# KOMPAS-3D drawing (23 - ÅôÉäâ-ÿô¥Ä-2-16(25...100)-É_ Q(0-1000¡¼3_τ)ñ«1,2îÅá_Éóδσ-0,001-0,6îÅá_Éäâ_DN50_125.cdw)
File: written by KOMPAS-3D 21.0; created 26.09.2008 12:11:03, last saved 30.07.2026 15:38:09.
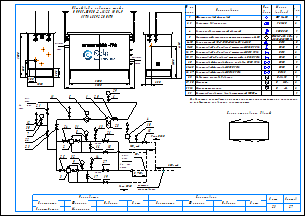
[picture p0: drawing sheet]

Sheets 1-2: A3, landscape

Document properties: Наименование: Макро:21; Автор: RaskoAdmin; Форматы листов документа: 2xA3; Полное имя файла: \\ur38nt01\Departments\КТО\КБ ПУРДГ\Заявки\Прайс-лист на типовые шкафы ГРПШ\ПУРДГ_стандарт_30_04_2026\ПУРДГ с РДГ(Н, В)\ПУРДГ-ШУЭО-2-16(25...100)-Р_ Q(0-1000нм3_ч)до1,2МПа_Рвых-0,001-0,6МПа_РДГ_DN50_125.cdw

Title block, sheet 1: Наименование: Пункт учета газа / ПУГ-Ш-400-Р / ЛГТИ.485922.001ТУ; designation: ЛГТИ.03.4411141; sheet number: 1; Количество листов документа: 2; organisation: ООО "ЭЛЬСТЕР Газэлектроника"; Форматы листов документа: A3; stored path: C:\Рабочие документы\Компас\ПУГ\Схема.cdw; Разработал: Устинов; Проверил: Кошкин; Утвердил: Кошкин
Title block, sheet 2: sheet number: 2; stored path: D:\Рабочие документы\Заявки\ПУРДГ\ПУРДГ-ШУЭО-2-100-Р 4411220.cdw; designation, second copy: ЛГТИ.03.4411141-

Views: Вид 1, Вид 2
Referenced files: wcvoit.frw
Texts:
  Normal
  № на
  схеме
  Усл.
  обозн.
  Марка
  (модель)
  Кол.
  Фильтр газовый фланцевый
  ФГ 16-50
  Регулятор давления газа
  РДГ-50
  Клапан предохранительный сбросной
  КПС DN20
  Измерительный комплекс с ротационным счетчиком Ду50
  СГ-ЭК-Р-(0,2...2,0)-
  Кран кнопочный VE-РАСКО-НЗ-1,6-G1/2-М20
  DN15
  Кран шаровой "под приварку" штуцерный DN20 PN16
  DN20
  Кран шаровой "под приварку" штуцерный DN15 PN16
  Кран шаровой "под приварку" штуцерный п/п DN20 PN16
  Кран шаровой фланцевый с мех. приводом DN50 PN16
  Кран шаровой фланцевый DN50 PN16
  Кран шаровой фланцевый DN125 PN16
  DN50
  DN125
  Индикатор перепада давления
  Манометр
  Манометр-напоромер
  Электрообогреватель взрывозащищенный 1000Вт
  Delta 15
  0...     МПа
  0...     кПа
  Общий вид и габариты шкафа
  ПУРДГ-ШУЭО-2-16(25...100)-Р
  Выход газа
  Вход газа
  logo-rasko-ge.png
  DN 1
  местное
  сопротивление
  Римп DN20
  Выход
  газа
  Р=     кПа
  Вход
  Р=       МПа
  PDI
  Схема открывания дверей
  Предприятие изготовитель может заменять комплектующие на аналогичные,
  не ухудшающие заявленных характеристик.
  Должность
  Конструктор
  Фамилия
  Подпись
  Дата
  Согласовано
  Максимкин
  Лист
  Листов
  POLYLINE_STYLE_0.18_RGB_0_0_0
  POLYLINE_STYLE_0.50_RGB_0_0_0
  POLYLINE_STYLE_0.34_RGB_0_0_0
  PHANTOM_RGB_0_0_0_SC_1_THICK_0.18
  K5LT_THIN_RGB_0_0_0_THICK_0.18
  K5LT32769_RGB_0_0_0_THICK_0.18
  K5LT12_RGB_0_0_0_SC_1_THICK_0.18
  K5LT_DASHED_RGB_0_0_0_SC_1_THICK_0.18
  ACISOTGL_RGB_0_0_0_SC_0.8_THICK_0.25
  CONTINUOUS_RGB_0_127_31_THICK_0.3
  CONTINUOUS_RGB_0_0_255_THICK_0.35
  CONTINUOUS_RGB_255_0_0_THICK_0.35
  POLYLINE_STYLE_0.25_RGB_0_0_0
  CONTINUOUS_RGB_0_0_0_THICK_0.5
  POLYLINE_STYLE_0.35_RGB_0_0_255
  CONTINUOUS_RGB_0_0_0_THICK_0.4
  CONTINUOUS_RGB_0_0_0_THICK_0.35
  НЕВИДИМАЯ_RGB_0_0_0_SC_0.3_THICK_0.25
  СONTINUOUS_RGB_0_0_0_THICK_0.25
  ОСЕВАЯ2_RGB_248_153_30_SC_0.3_THICK_0.25
  Без оформления
Dimensions and other numbers on the sheet: 1; 2, 3; 2; 4; 5; 6-10; 11-15; 16, 17; 18, 19; 20; 21-25; 26, 27; 28; 29, 30; 31, 32; 33; 1500; 250; 300; 1050; 550; 305; 3000; 4130; 2000; 3300; 5,,,7DN 1; 7; 30; 12; 21; 22; 23; 11; 6; 29; 24; 31; 8; 13; 26; 18; 10; 15; 25; 32; 9; 3; 14; 27; 19; 16; 17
